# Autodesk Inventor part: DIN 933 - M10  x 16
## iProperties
Comments: To add or edit properties for Autodesk Inventor files, use iProperties.
Created: 2003-09
Part Number: DIN 933 - M10  x 16
Vendor: Autodesk Inc.
Document SubType Name: Modeling
Designer: lamberj
Material: Default
Description: Hex-Head Bolt
Standard: DIN 933
Manufacturer: Standard
Standards Organization: Custom
Alert: To add or edit properties for Autodesk Inventor files, use iProperties.
Control State: 0
Master: False
Checked Out: False
Shininess: 64.0
Length Units: 11269
Angle Units: 11279
Time Units: 11290
Mass Units: 11283
Length Display Precision: 3
Angle Display Precision: 2
Compacted: True
EGR: 1
Classification: un/spsc 31161513
Density: 0.0
Volumn: 0.0
Area: 0.0
PropertySet Name: Model Information
Author: lamberj
Revision Number: 5
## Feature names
1. Body [Revolution]
2. Head [Extrusion]
3. Chamfer1 [Revolution]
4. Chamfer2
